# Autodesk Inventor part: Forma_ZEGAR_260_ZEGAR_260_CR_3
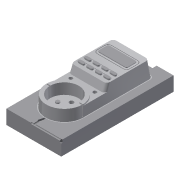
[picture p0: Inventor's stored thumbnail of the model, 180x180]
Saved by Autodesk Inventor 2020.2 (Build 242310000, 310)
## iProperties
Created: 2015-01
Part Number: Forma_ZEGAR_260_ZEGAR_260_CR_3
Material: Ogólny
Document SubType Name: Modeling
Designer: F.Stasiak
Density: 1 g/cm^3
Appearance: Domyślna
Catalog Web Link: www.expertbooks.pl
Manager: www.cadconsulting.pl
Company: Fabian Stasiak CAD Consulting
Author: F.Stasiak
Subject: Zbiór ćwiczeń. Autodesk Inventor 2020. Kurs Professional
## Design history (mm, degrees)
node "Forma_ZEGAR_260_ZEGAR_260_CR_Base"
feature "Rzeźbienie3"
feature "Bryła5::Forma_ZEGAR_260_ZEGAR_260_CR_Base"
tag "Bryła wyprowadzona1"
node "Bryła1"
feature "Forma_ZEGAR_260_ZEGAR_260_CR_Base_Bodies"
feature "Powierzchnia3"
body "Srf3"
